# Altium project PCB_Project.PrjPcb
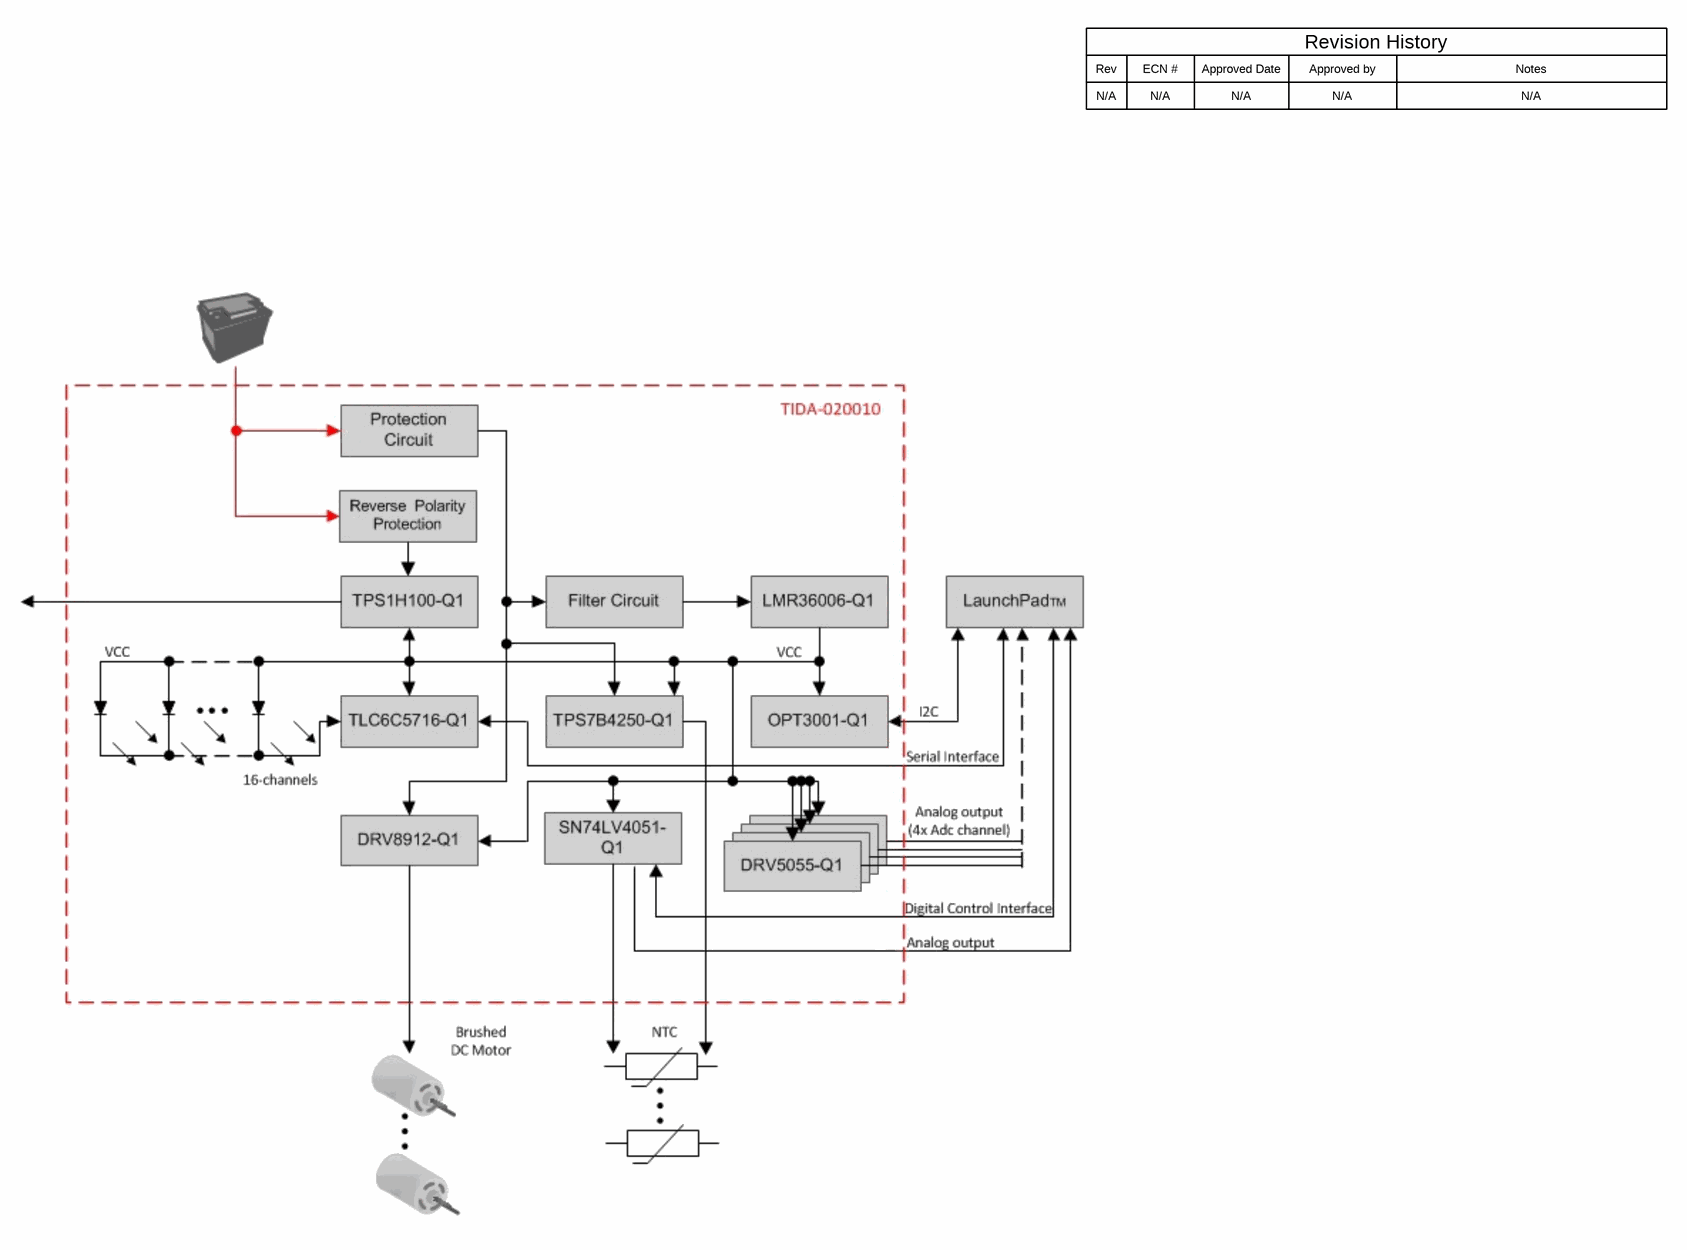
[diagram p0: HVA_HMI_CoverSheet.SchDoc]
CopyrightYear: 2018; PCB_Layout: Levan Bidzishvili; PCB_Rev: E1; PRJ_Customer: Public Release; PRJ_Engineer: Levan Bidzishvili; PRJ_Number: TIDA-020010; PRJ_Title: Automotive HVAC Control with HMI Reference Design; SCH_Rev: E1; TechSupport: http://www.ti.com/support; TID: 020010
4 sheets, 120 parts. Net scope: global (net labels, ports and power ports of the same name join across sheets).
Board file: PCB_Project_PCB.PcbDoc
Sheets:
  HVA_HMI_CoverSheet.SchDoc
  HVA_HMI_p1.SchDoc
  HVA_HMI_p2.SchDoc
  HVAC_HMI_EVM_Hardware.SchDoc

## Sheet HVA_HMI_CoverSheet.SchDoc
size 431 x 279 mm; Date: Not shown in title block; ApprovedBy: Not shown in title block; CheckedBy: Not shown in title block; Author: Not shown in title block; CompanyName: Not shown in title block; Engineer: Not shown in title block; Organization: Not shown in title block; Address1: Not shown in title block; Address2: Not shown in title block; Address3: Not shown in title block; Address4: Not shown in title block; DocumentNumber: 1; Revision: Use project parameter SCH_Rev; SheetNumber: 1; SheetTotal: 3; PageSetup: Record=PageOptions¦CenterHorizontal=True¦CenterVertical=True¦PrintScale=1.00¦XCorrection=1.00¦YCorrection=1.00¦PrintKind=0¦BorderSize=5000000¦LeftOffset=0¦BottomOffset=0¦Orientation=2¦PaperLength=1000¦PaperWidth=1000¦Scale=100¦PaperSource=15¦PrintQuality=600¦MediaType=1¦DitherType=10¦PaperKind=Letter¦PrintScaleMode=1

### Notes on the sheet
- Rev
- N/A
- ECN #
- Approved Date
- Approved by
- Revision History
- Notes

## Sheet HVA_HMI_p1.SchDoc
size 431 x 279 mm; Date: Not shown in title block; ApprovedBy: Not shown in title block; CheckedBy: Not shown in title block; Author: Not shown in title block; CompanyName: Not shown in title block; Engineer: Not shown in title block; Organization: Not shown in title block; Address1: Not shown in title block; Address2: Not shown in title block; Address3: Not shown in title block; Address4: Not shown in title block; DocumentNumber: 1; Revision: Use project parameter SCH_Rev; SheetNumber: 2; SheetTotal: 3; PageSetup: Record=PageOptions¦CenterHorizontal=True¦CenterVertical=True¦PrintScale=1.00¦XCorrection=1.00¦YCorrection=1.00¦PrintKind=0¦BorderSize=5000000¦LeftOffset=0¦BottomOffset=0¦Orientation=2¦PaperLength=1000¦PaperWidth=1000¦Scale=100¦PaperSource=15¦PrintQuality=600¦MediaType=1¦DitherType=10¦PaperKind=Letter¦PrintScaleMode=1
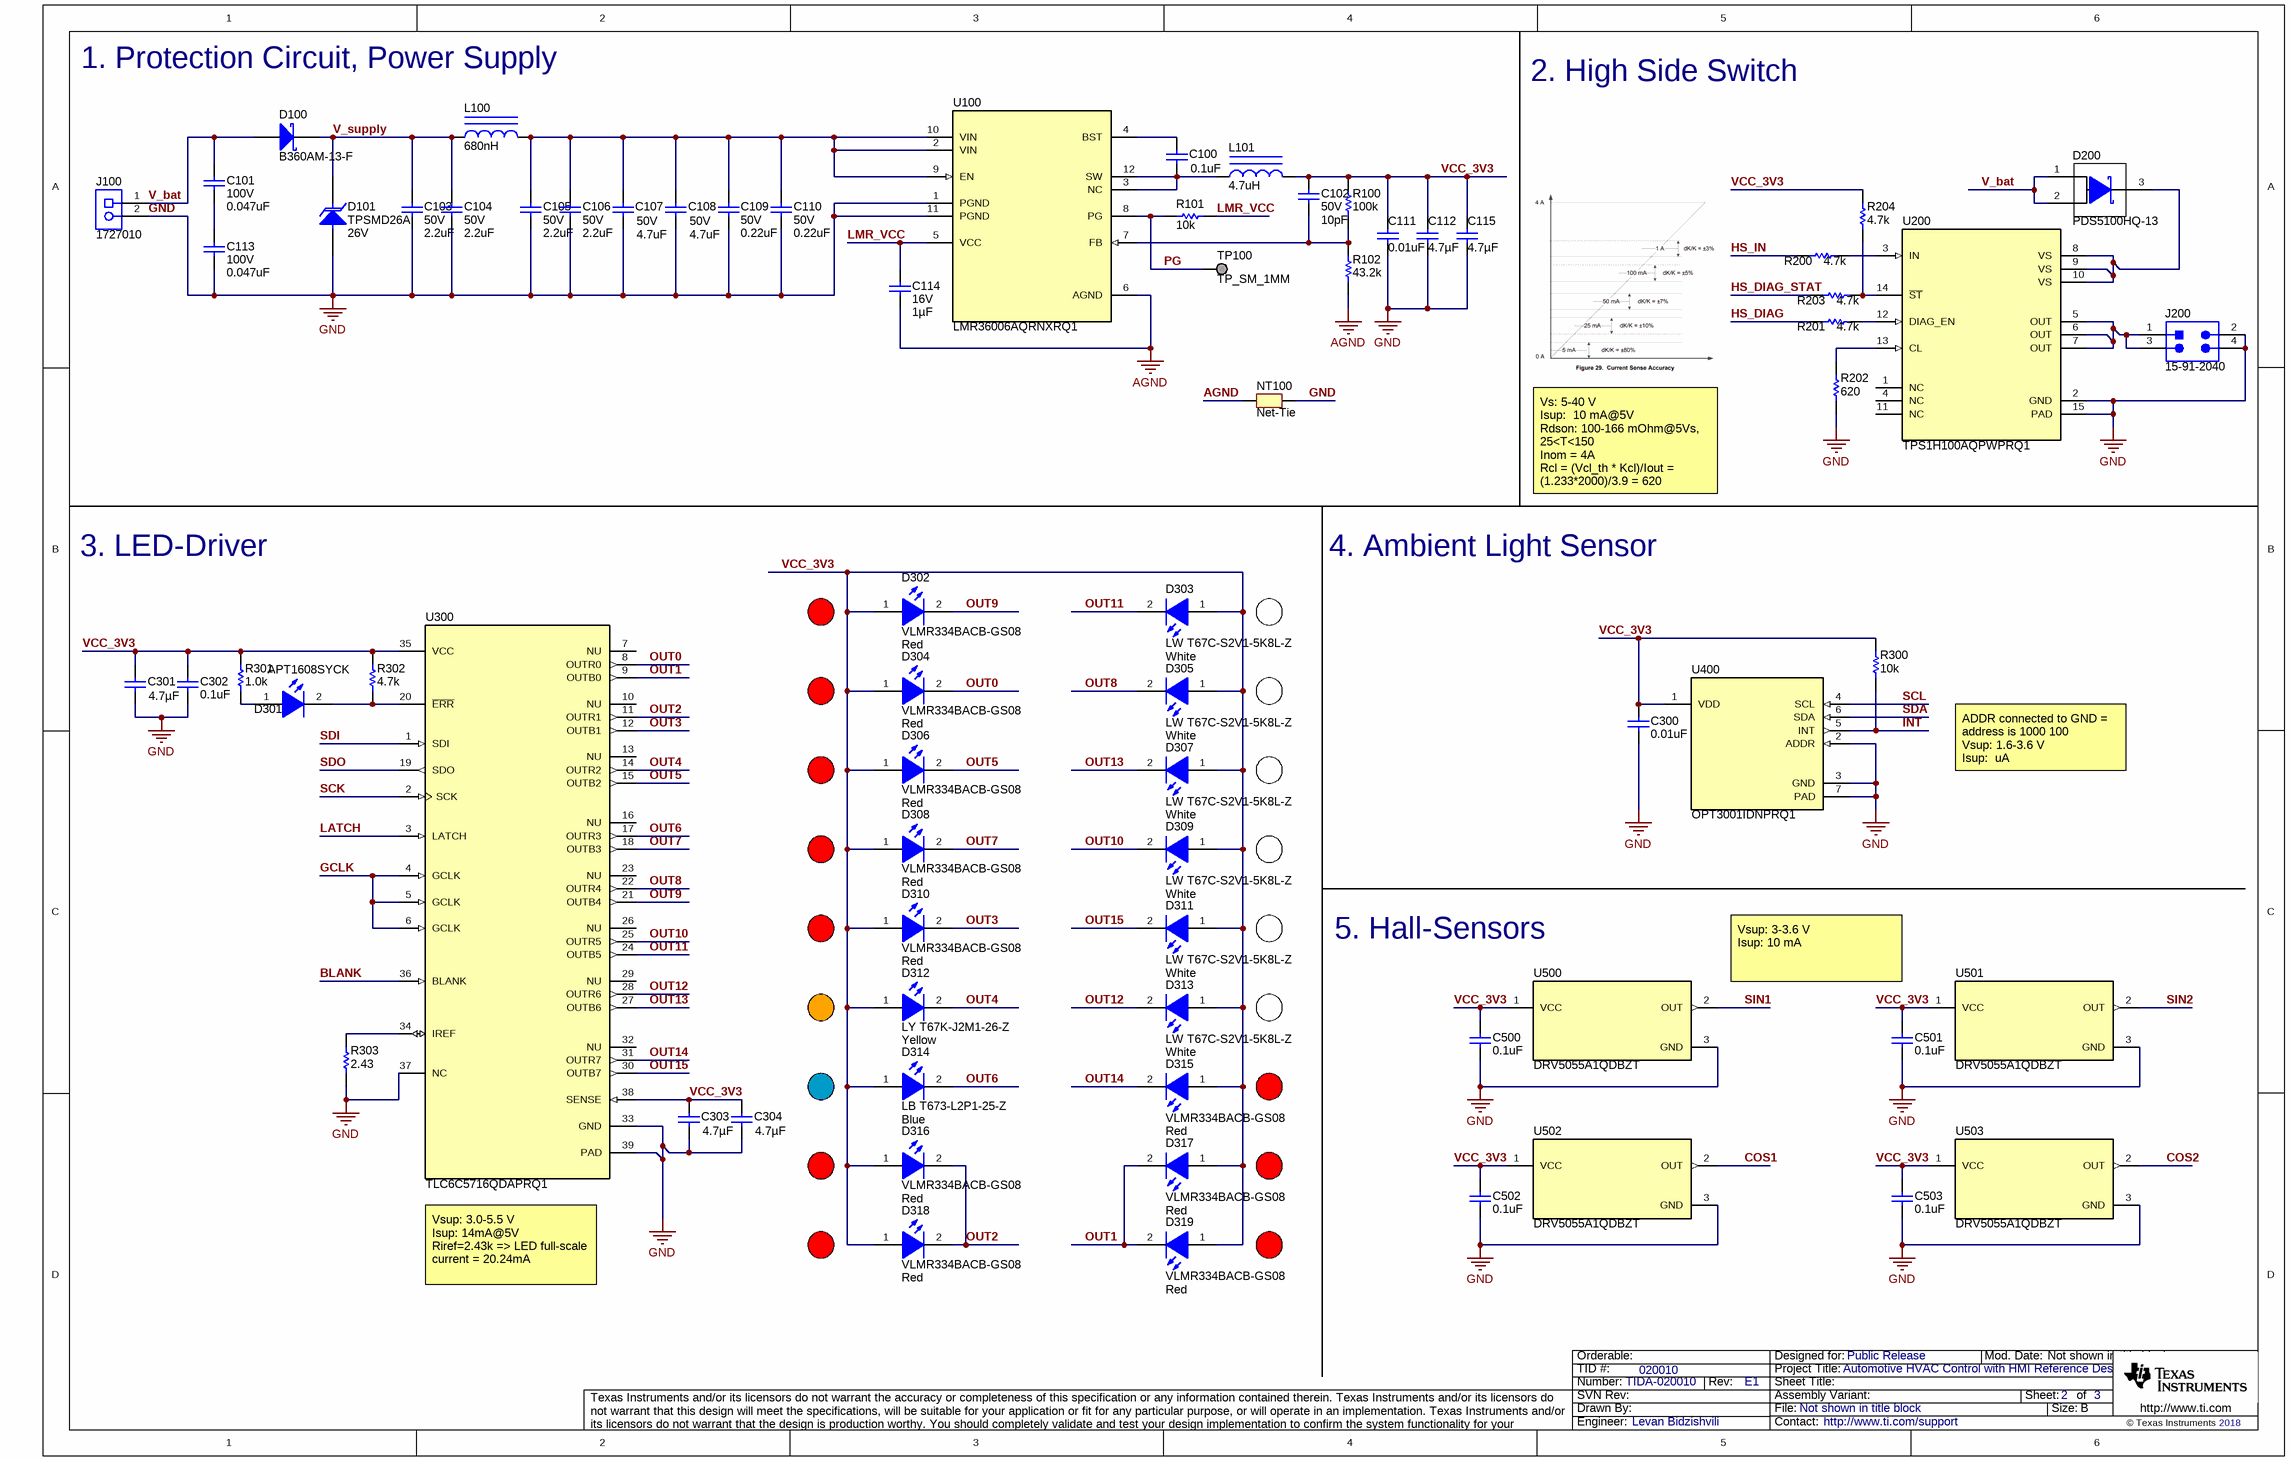
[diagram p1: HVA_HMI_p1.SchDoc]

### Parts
C100  ValueDisplayed: 0.1uF  [0603S]  (hidden comment: CGA3E2X7R1H104K080AA)
C101  VDC_V: 100V  ValueDisplayed: 0.047uF  [0805_HV]  (hidden comment: CGA4J2X7R2A473K125AA)
C102  VDC_V: 50V  ValueDisplayed: 10pF  [0603S]  (hidden comment: CGA3E2C0G1H100D080AA)
C103  VDC_V: 50V  ValueDisplayed: 2.2uF  [0805_HV]  (hidden comment: CGA4J3X7R1H225K125AB)
C104  VDC_V: 50V  ValueDisplayed: 2.2uF  [0805_HV]  (hidden comment: CGA4J3X7R1H225K125AB)
C105  VDC_V: 50V  ValueDisplayed: 2.2uF  [0805_HV]  (hidden comment: CGA4J3X7R1H225K125AB)
C106  VDC_V: 50V  ValueDisplayed: 2.2uF  [0805_HV]  (hidden comment: CGA4J3X7R1H225K125AB)
C107  VDC_V: 50V  ValueDisplayed: 4.7uF  [0805_HV]  (hidden comment: GRT21BR61H475KE13L)
C108  VDC_V: 50V  ValueDisplayed: 4.7uF  [0805_HV]  (hidden comment: GRT21BR61H475KE13L)
C109  VDC_V: 50V  ValueDisplayed: 0.22uF  [0603S]  (hidden comment: GCM188R71H224KA64D)
C110  VDC_V: 50V  ValueDisplayed: 0.22uF  [0603S]  (hidden comment: GCM188R71H224KA64D)
C111  ValueDisplayed: 0.01uF  [0603S]  (hidden comment: C0603C103J3GECAUTO)
C112  ValueDisplayed: 4.7µF  [0805_HV]  (hidden comment: CGA4J1X7R1E475K125AC)
C113  VDC_V: 100V  ValueDisplayed: 0.047uF  [0805_HV]  (hidden comment: CGA4J2X7R2A473K125AA)
C114  VDC_V: 16V  ValueDisplayed: 1µF  [0603S]  (hidden comment: CGA3E1X7R1C105K080AC)
C115  ValueDisplayed: 4.7µF  [0805_HV]  (hidden comment: CGA4J1X7R1E475K125AC)
C300  ValueDisplayed: 0.01uF  [0603]  (hidden comment: C0603C103J3GECAUTO)
C301  ValueDisplayed: 4.7µF  [0805L]  (hidden comment: CGA4J1X7R1E475K125AC)
C302  ValueDisplayed: 0.1uF  [0603]  (hidden comment: CGJ3E2X7R1C104K080AA)
C303  ValueDisplayed: 4.7µF  [0805L]  (hidden comment: CGA4J1X7R1E475K125AC)
C304  ValueDisplayed: 4.7µF  [0805L]  (hidden comment: CGA4J1X7R1E475K125AC)
C500  ValueDisplayed: 0.1uF  [0603]  (hidden comment: CGJ3E2X7R1C104K080AA)
C501  ValueDisplayed: 0.1uF  [0603]  (hidden comment: CGJ3E2X7R1C104K080AA)
C502  ValueDisplayed: 0.1uF  [0603]  (hidden comment: CGJ3E2X7R1C104K080AA)
C503  ValueDisplayed: 0.1uF  [0603]  (hidden comment: CGJ3E2X7R1C104K080AA)
D100  B360AM-13-F  [SMA]
D101  TPSMD26A  value 26V  [SMC_265]
D200  PDS5100HQ-13  [POWERDI5]
D301  APT1608SYCK  [APT1608_Yellow]
D302  VLMR334BACB-GS08  value Red  [VLMR334_Red]
D303  LW T67C-S2V1-5K8L-Z  value White  [LW_T67C_White]
D304  VLMR334BACB-GS08  value Red  [VLMR334_Red]
D305  LW T67C-S2V1-5K8L-Z  value White  [LW_T67C_White]
D306  VLMR334BACB-GS08  value Red  [VLMR334_Red]
D307  LW T67C-S2V1-5K8L-Z  value White  [LW_T67C_White]
D308  VLMR334BACB-GS08  value Red  [VLMR334_Red]
D309  LW T67C-S2V1-5K8L-Z  value White  [LW_T67C_White]
D310  VLMR334BACB-GS08  value Red  [VLMR334_Red]
D311  LW T67C-S2V1-5K8L-Z  value White  [LW_T67C_White]
D312  LY T67K-J2M1-26-Z  value Yellow  [LY_T67K_Yellow]
D313  LW T67C-S2V1-5K8L-Z  value White  [LW_T67C_White]
D314  LB T673-L2P1-25-Z  value Blue  [LB_T673_Blue]
D315  VLMR334BACB-GS08  value Red  [VLMR334_Red]
D316  VLMR334BACB-GS08  value Red  [VLMR334_Red]
D317  VLMR334BACB-GS08  value Red  [VLMR334_Red]
D318  VLMR334BACB-GS08  value Red  [VLMR334_Red]
D319  VLMR334BACB-GS08  value Red  [VLMR334_Red]
J100  1727010  [PhoenixConact_1727010]
J200  15-91-2040  [Molex_15-91-2040]
L100  ValueDisplayed: 680nH  [DFE252012P]  (hidden comment: DFE252012PD-R68M)
L101  ValueDisplayed: 4.7uH  [DFE252012P]  (hidden comment: DFE252012PD-4R7M)
NT100  Net-Tie  [Net-Tie_50milWide_30milLong]  (net tie, no BOM)
R100  ValueDisplayed: 100k  [0603S]  (hidden comment: ERJ-3GEYJ104V)
R101  ValueDisplayed: 10k  [0603S]  (hidden comment: CRCW060310K0JNEA)
R102  ValueDisplayed: 43.2k  [0603S]  (hidden comment: CRCW060343K2FKEA)
R200  ValueDisplayed: 4.7k  [0603]  (hidden comment: ERJ-3GEYJ472V)
R201  ValueDisplayed: 4.7k  [0603]  (hidden comment: ERJ-3GEYJ472V)
R202  ValueDisplayed: 620  [0805_HV]  (hidden comment: RR1220P-621-D)
R203  ValueDisplayed: 4.7k  [0603]  (hidden comment: ERJ-3GEYJ472V)
R204  ValueDisplayed: 4.7k  [0603S]  (hidden comment: ERJ-3GEYJ472V)
R300  ValueDisplayed: 10k  [0603]  (hidden comment: CRCW060310K0JNEA)
R301  ValueDisplayed: 1.0k  [0603]  (hidden comment: RCA06031K00JNEA)
R302  ValueDisplayed: 4.7k  [0603]  (hidden comment: ERJ-3GEYJ472V)
R303  ValueDisplayed: 2.43  [0603S]  (hidden comment: CRCW06032R43FKEA)
TP100  TP_SM_1MM  [TP_SM_1MM]  (no BOM)
U100  LMR36006AQRNXRQ1  [RNX0012B]
U200  TPS1H100AQPWPRQ1  [PWP0014C_N]
U300  TLC6C5716QDAPRQ1  [DAP0038E]
U400  OPT3001IDNPRQ1  [DNP0006A]
U500  DRV5055A1QDBZT  [DBZ0003A_N]
U501  DRV5055A1QDBZT  [DBZ0003A_N]
U502  DRV5055A1QDBZT  [DBZ0003A_N]
U503  DRV5055A1QDBZT  [DBZ0003A_N]

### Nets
AGND: C114.1 NT100.1 R102.1 U100.6(AGND)
GND: C103.2 C104.2 C105.2 C106.2 C107.2 C108.2 C109.2 C110.2 C111.2 C112.2 C113.2 C115.2 C300.2 C301.2 C302.2 C303.2 C304.2 C500.2 C501.2 C502.2 C503.2 D101.2(A) J100.2 J200.2 J200.4 NT100.2 R202.1 R303.1 U100.1(PGND) U100.11(PGND) U200.2(GND) U200.15(PAD) U300.33(GND) U300.37(NC) U300.39(PAD) U400.2(ADDR) U400.3(GND) U400.7(PAD) U500.3(GND) U501.3(GND) U502.3(GND) U503.3(GND)
BLANK: U300.36(BLANK)
COS1: U502.2(OUT)
COS2: U503.2(OUT)
GCLK: U300.4(GCLK) U300.5(GCLK) U300.6(GCLK)
HS_DIAG: R201.2
HS_DIAG_STAT: R203.2
HS_IN: R200.2
INT: R300.1 U400.5(INT)
LATCH: U300.3(LATCH)
LMR_VCC: C114.2 R101.2 U100.5(VCC)
OUT0: D304.2(K) U300.8(OUTR0)
OUT1: D317.2(K) D319.2(K) U300.9(OUTB0)
OUT2: D316.2(K) D318.2(K) U300.11(OUTR1)
OUT3: D310.2(K) U300.12(OUTB1)
OUT4: D312.2(K) U300.14(OUTR2)
OUT5: D306.2(K) U300.15(OUTB2)
OUT6: D314.2(K) U300.17(OUTR3)
OUT7: D308.2(K) U300.18(OUTB3)
OUT8: D305.2(K) U300.22(OUTR4)
OUT9: D302.2(K) U300.21(OUTB4)
OUT10: D309.2(K) U300.25(OUTR5)
OUT11: D303.2(K) U300.24(OUTB5)
OUT12: D313.2(K) U300.28(OUTR6)
OUT13: D307.2(K) U300.27(OUTB6)
OUT14: D315.2(K) U300.31(OUTR7)
OUT15: D311.2(K) U300.30(OUTB7)
PG: R101.1 TP100.1 U100.8(PG)
SCK: U300.2(SCK)
SCL: U400.4(SCL)
SDA: U400.6(SDA)
SDI: U300.1(SDI)
SDO: U300.19(SDO)
SIN1: U500.2(OUT)
SIN2: U501.2(OUT)
V_bat: C101.1 D100.2(A) D200.1(A) D200.2(A) J100.1
V_supply: C103.1 C104.1 D100.1(K) D101.1(K) L100.1
VCC_3V3: C102.1 C111.1 C112.1 C115.1 C300.1 C301.1 C302.1 C303.1 C304.1 C500.1 C501.1 C502.1 C503.1 D302.1(A) D303.1(A) D304.1(A) D305.1(A) D306.1(A) D307.1(A) D308.1(A) D309.1(A) D310.1(A) D311.1(A) D312.1(A) D313.1(A) D314.1(A) D315.1(A) D316.1(A) D317.1(A) D318.1(A) D319.1(A) L101.2 R100.2 R204.2 R300.2 R301.2 R302.1 U300.35(VCC) U300.38(SENSE) U400.1(VDD) U500.1(VCC) U501.1(VCC) U502.1(VCC) U503.1(VCC)
NetC100_1: C100.1 L101.1 U100.3(NC) U100.12(SW)
NetC100_2: C100.2 U100.4(BST)
NetC101_2: C101.2 C113.1
NetC102_2: C102.2 R100.1 R102.2 U100.7(FB)
NetC105_1: C105.1 C106.1 C107.1 C108.1 C109.1 C110.1 L100.2 U100.2(VIN) U100.9(EN) U100.10(VIN)
NetD200_3: D200.3(K) U200.8(VS) U200.9(VS) U200.10(VS)
NetD301_1: D301.1(A) R301.1
NetD301_2: D301.2(K) R302.2 U300.20(~{ERR})
NetJ200_1: J200.1 J200.3 U200.5(OUT) U200.6(OUT) U200.7(OUT)
NetR200_1: R200.1 U200.3(IN)
NetR201_1: R201.1 U200.12(DIAG_EN)
NetR202_2: R202.2 U200.13(CL)
NetR203_1: R203.1 R204.1 U200.14(~{ST})
NetR303_2: R303.2 U300.34(IREF)

Not connected (* = marked no-connect by the designer): U200 1(NC) 4(NC) 11(NC); U300 7(NU) 10(NU) 13(NU) 16(NU) 23(NU) 26(NU) 29(NU) 32(NU)

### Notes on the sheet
- 1. Protection Circuit, Power Supply
- 2. High Side Switch
- standoff voltage should be above 24V because of jump-start condition. better would be 26V
  SMAJ26CAHE3/61 VISHAY
  TPS... littlefuse
- (near R102) voltage devider is a place holder
- 06A: 600mA, 400kHz
  06C: 600ma, 2.1Mhz
  FSC3: my choice
- Vs: 5-40 V
  Isup:  10 mA@5V
  Rdson: 100-166 mOhm@5Vs, 25<T<150
  Inom = 4A
  Rcl = (Vcl_th * Kcl)/Iout = (1.233*2000)/3.9 = 620
- 3. LED-Driver
- 4. Ambient Light Sensor
- (near D302) LED's are place holders here.
  they should choosen properly
- ADDR connected to GND = address is 1000 100
  Vsup: 1.6-3.6 V
  Isup:  uA
- 5. Hall-Sensors
- Vsup: 3-3.6 V
  Isup: 10 mA
- (near C304) Sense wire is connected to source rail (V_3V3) in this case.
- Vsup: 3.0-5.5 V
  Isup: 14mA@5V
  Riref=2.43k => LED full-scale current = 20.24mA

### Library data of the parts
C100 = CMP-0007078-4: CAP, CERM, 0.1 uF, 50 V, +/- 10%, X7R, AEC-Q200 Grade 1, 0603; Manufacturer: TDK; TaMin_C: -55°C; Polarized: N; SizeAreaWB_mm2: 4.68; Value1: 0.0296 ohm; U/M: EA; Value: 0.1uF; TaMax_C: 125°C; SizeZ_mm: 1; SizeX_mm: 1.6; SizeY_mm: 0.8; Cap_Case: 0603; Value2: 50V; SizeArea_mm2: 1.28; CompType: Capacitor; AEC Qualified: Y; Cap_F: 100nF; AEC Category: Q200; ESR_ohm: 0.0296; IRMS_A: 9.7199dA
C101 C113 = CMP-0007970-2: CAP, CERM, 0.047 uF, 100 V, +/- 10%, X7R, AEC-Q200 Grade 1, 0805; Manufacturer: TDK; TaMin_C: -55°C; ESR_ohm: 0.049089; Polarized: N; SizeAreaWB_mm2: 6.75; Value1: 0.049089 ohm; U/M: EA; TaMax_C: 125°C; SizeZ_mm: 1.45; SizeX_mm: 2; SizeY_mm: 1.25; Cap_Case: 0805; SizeArea_mm2: 2.5; CompType: Capacitor; AEC Qualified: Y; Cap_F: 47nF; IRMS_A: 9.63171dA; AEC Grade: 1; AEC Category: Q200
C102 = CMP-0007069-4: CAP, CERM, 10 pF, 50 V, +/- 5%, C0G/NP0, AEC-Q200 Grade 1, 0603; Manufacturer: TDK; TaMin_C: -55°C; Polarized: N; SizeAreaWB_mm2: 4.68; Value1: Unknown; U/M: EA; Value: 10pF; TaMax_C: 125°C; SizeZ_mm: 1; SizeX_mm: 1.6; SizeY_mm: 0.8; Cap_Case: 0603; SizeArea_mm2: 1.28; CompType: Capacitor; AEC Qualified: Y; AEC Category: Q200
C103-C106 = CMP-0007977-2: CAP, CERM, 2.2 uF, 50 V, +/- 10%, X7R, AEC-Q200 Grade 1, 0805; Manufacturer: TDK; TaMin_C: -55°C; ESR_ohm: 3.288m; Polarized: N; SizeAreaWB_mm2: 6.75; Value1: 0.003288 ohm; U/M: EA; Value: 2.2uF; TaMax_C: 125°C; SizeZ_mm: 1.45; SizeX_mm: 2; SizeY_mm: 1.25; Cap_Case: 0805; SizeArea_mm2: 2.5; AEC Qualified: Y; Cap_F: 2.2µF; IRMS_A: 3.60029A; AEC Grade: 1; AEC Category: Q200
C107 C108 = CMP-0008380-2: CAP, CERM, 4.7 uF, 50 V, +/- 10%, X5R, AEC-Q200 Grade 3, 0805; Manufacturer: MuRata; TaMin_C: -55°C; Polarized: N; SizeAreaWB_mm2: 6.75; Value1: Unknown; U/M: EA; Value: 4.7uF; TaMax_C: 85°C; SizeZ_mm: 1.45; SizeX_mm: 2; SizeY_mm: 1.25; Cap_Case: 0805; SizeArea_mm2: 2.5; CompType: Capacitor; AEC Qualified: Y; Cap_F: 4.7µF; AEC Grade: 3; AEC Category: Q200
C109 C110 = CMP-0007145-4: CAP, CERM, 0.22 uF, 50 V, +/- 10%, X7R, AEC-Q200 Grade 1, 0603; Manufacturer: MuRata; TaMin_C: -55°C; Polarized: N; SizeAreaWB_mm2: 4.68; Value1: Unknown; U/M: EA; Value: 0.22uF; TaMax_C: 125°C; SizeZ_mm: 1; SizeX_mm: 1.6; SizeY_mm: 0.8; Cap_Case: 0603; SizeArea_mm2: 1.28; CompType: Capacitor; AEC Qualified: Y; Cap_F: 220nF; AEC Category: Q200
C111 = CMP-0006849-4: CAP, CERM, 0.01 uF, 25 V, +/- 5%, C0G/NP0, AEC-Q200 Grade 1, 0603; Manufacturer: Kemet; TaMin_C: -55°C; Polarized: N; SizeAreaWB_mm2: 4.68; Value1: Unknown; U/M: EA; Value: 0.01uF; TaMax_C: 125°C; SizeZ_mm: 1; SizeX_mm: 1.6; SizeY_mm: 0.8; Cap_Case: 0603; Value2: 25V; SizeArea_mm2: 1.28; CompType: Capacitor; AEC Qualified: Y; Cap_F: 10nF; AEC Category: Q200
C112 C115 C301 C303 C304 = CMP-0076706-1: CAP, CERM, 4.7 µF, 25 V,+/- 10%, X7R, AEC-Q200 Grade 1, 0805; Manufacturer: TDK; SizeAreaWB_mm2: 6.75; SizeArea_mm2: 2.5; AEC Qualified: Y; AEC Category: Q200; Value: 4.7uF; TaMax_C: 125°C; SizeZ_mm: 1.45; AEC Grade: 1; Polarized: N; TaMin_C: -55°C; VDC_V: 25V; SizeY_mm: 1.25; U/M: EA; CompType: Capacitor; SizeX_mm: 2.0; Cap_Case: 2x1.25x1.25mm
C114 = CMP-0079607-1: CAP, CERM, 1 µF, 16 V,+/- 10%, X7R, AEC-Q200 Grade 1, 0603; Manufacturer: TDK; TaMin_C: -55°C; Polarized: N; SizeAreaWB_mm2: 4.68; U/M: EA; Value: 1uF; TaMax_C: 125°C; SizeZ_mm: 1; SizeX_mm: 1.6; SizeY_mm: 0.8; Cap_Case: 0603; SizeArea_mm2: 1.28; CompType: Capacitor; AEC Qualified: Y; AEC Category: Q200
C300 = CMP-0006849-4: CAP, CERM, 0.01 uF, 25 V, +/- 5%, C0G/NP0, AEC-Q200 Grade 1, 0603; Manufacturer: Kemet; TaMin_C: -55°C; Polarized: N; SizeAreaWB_mm2: 4.68; Value1: Unknown; U/M: EA; Value: 0.01uF; TaMax_C: 125°C; SizeZ_mm: 1; SizeX_mm: 1.6; SizeY_mm: 0.8; Value2: 25V; SizeArea_mm2: 1.28; CompType: Capacitor; AEC Qualified: Y; Cap_F: 10nF; AEC Category: Q200
C302 C500-C503 = CMP-0007106-4: CAP, CERM, 0.1 uF, 16 V, +/- 10%, X7R, AEC-Q200 Grade 1, 0603; Manufacturer: TDK; TaMin_C: -55°C; Polarized: N; SizeAreaWB_mm2: 4.68; Value1: Unknown; U/M: EA; Value: 0.1uF; TaMax_C: 125°C; SizeZ_mm: 1; SizeX_mm: 1.6; SizeY_mm: 0.8; Value2: 16V; SizeArea_mm2: 1.28; CompType: Capacitor; AEC Qualified: Y; Cap_F: 100nF; AEC Category: Q200
D100 = CMP-0028785-1: Diode, Schottky, 60 V, 3 A, AEC-Q101, SMA; Manufacturer: Diodes Inc.; Io_A: 3A; Green_Lifecycle: Not Set; SizeAreaWB_mm2: 37.3428; Vr_V: 60V; Green_REACh: Incomplete; TJmax_C: 150°C; U/M: EA; Value: 60V; SizeZ_mm: 2.87; SizeX_mm: 5.59; SizeY_mm: 2.92; Vf_V: 7dV; Value2: 0.7V; SizeArea_mm2: 16.3228; AEC Qualified: Y; AEC Category: Q101
D101 = CMP-0005729-2: Diode, TVS, Uni, 26 V, 42.1 Vc, AEC-Q101, SMC; Manufacturer: Littelfuse; Power_W: 6.5W; SizeAreaWB_mm2: 78.5757; RJA_CperW: 75; U/M: EA; SizeZ_mm: 2.62; SizeX_mm: 7.94; SizeY_mm: 5.905; SizeArea_mm2: 46.8857; AEC Qualified: Y; AEC Category: Q101
D200 = CMP-0080010-1: Diode, Schottky, 100 V, 5 A, AEC-Q101, PowerDI5; Manufacturer: Diodes Inc.; SizeAreaWB_mm2: 49.56; Vr_V: 100V; SizeArea_mm2: 24.96; AEC Qualified: Y; TJmax_C: 175°C; AEC Category: Q101; Value: 100V; SizeZ_mm: 1.05; Io_A: 5A; Vf_V: 7.1dV; SizeY_mm: 3.9; Value2: 0.71V; SizeX_mm: 6.4; RJC_CperW: 5
D301 = CMP-0002944-2: LED, Yellow, SMD; Manufacturer: Kingbright; Io_A: 20mA; Vr_V: 5V; Tjmax_C: 85°C; Value1: W; U/M: EA; Angle: 120; Ir_A: 10µA; Vf_V: 2.5V
D302 D304 D306 D308 D310 D315-D319 = CMP-0067668-1: LED, Red, SMD; Manufacturer: Vishay-Semiconductor; Io_A: 50mA; Power_TotalModule: 200mW; SizeAreaWB_mm2: 17.1; Vr_V: 5V; Tjmax_C: 125°C; Value1: 0.2W; U/M: EA; Angle: 120.0; SizeZ_mm: 1.85; SizeX_mm: 3.5; SizeY_mm: 2.8; Ir_A: 10µA; Vf_V: 2.2V; SizeArea_mm2: 9.8; Type: AlInGaP
D303 D305 D307 D309 D311 D313 = CMP-0003011-2: LED, White, SMD; Manufacturer: OSRAM; Io_A: 20mA; SizeAreaWB_mm2: 17.1; Vr_V: 5V; Tjmax_C: 110°C; Value1: W; U/M: EA; Angle: 120; SizeZ_mm: 2.1; SizeX_mm: 2.8; SizeY_mm: 3.5; Ir_A: 10µA; Vf_V: 3.2V; SizeArea_mm2: 9.8; Type: InGaN
D312 = CMP-0003012-2: LED, Yellow, SMD; Manufacturer: OSRAM; Io_A: 20mA; SizeAreaWB_mm2: 17.1; Vr_V: 12V; Tjmax_C: 125°C; Value1: W; U/M: EA; Angle: 120; SizeZ_mm: 2.1; SizeX_mm: 2.8; SizeY_mm: 3.5; Ir_A: 10µA; Vf_V: 1.8V; SizeArea_mm2: 9.8; Type: AlInGaP
D314 = CMP-0003013-2: LED, Blue, SMD; Manufacturer: OSRAM; Io_A: 20mA; SizeAreaWB_mm2: 17.1; Vr_V: 5V; Tjmax_C: 110°C; Value1: W; U/M: EA; Angle: 120; SizeZ_mm: 2.1; SizeX_mm: 2.8; SizeY_mm: 3.5; Ir_A: 10µA; Vf_V: 3.1V; SizeArea_mm2: 9.8; Type: InGaN
J100 = CMP-0055472-1: Conn Term Block, 2POS, 3.81mm, TH; Manufacturer: Phoenix Contact; CT: TRUE; Green_REACh: Incomplete; CompType: Terminal Block; CNHeader: FALSE; Green_Lifecycle: Not Set
J200 = CMP-0055317-1: Header, 100mil, 2x2, Tin, SMT; Manufacturer: Molex; CNHeader: TRUE; Green_Lifecycle: Active; Green_REACh: Passed; CT: FALSE
L100 = CMP-0058945-1: Inductor, Shielded, Metal Composite, 680 nH, 3.5 A, 0.03 ohm, AEC-Q200 Grade 1, SMD; Manufacturer: MuRata Toko; Isat: 4.3A @ 30% inductance drop; Irms: 3.5A @ 40C rise; SizeAreaWB_mm2: 10.5; DCR_ohm: 0.03; Value: 680nH; Imax_A: 3.5A; SizeZ_mm: 1.2; SizeX_mm: 2.5; SizeY_mm: 2; SizeArea_mm2: 5; AEC Qualified: Y; AEC Grade: 1; AEC Category: Q200
L101 = CMP-0058942-1: Inductor, Shielded, Metal Composite, 4.7 uH, 1.4 A, 0.165 ohm, AEC-Q200 Grade 1, SMD; Manufacturer: MuRata Toko; Isat: 1.9A @ 30% inductance drop; Irms: 1.4A @ 40C rise; SizeAreaWB_mm2: 10.5; DCR_ohm: 1.65d; Value: 4.7uH; Imax_A: 1.4A; SizeZ_mm: 1.2; SizeX_mm: 2.5; SizeY_mm: 2; SizeArea_mm2: 5; Ind_H: 4.7µH; AEC Qualified: Y; AEC Grade: 1; AEC Category: Q200
NT100 = CMP-0078142-2: Single point connection between nets.
R100 = CMP-0025875-3: RES, 100 k, 5%, 0.1 W, AEC-Q200 Grade 0, 0603; Manufacturer: Panasonic; Power_W: 100mW; TempCo: 200 ppm/C; U/M: EA; Value: 100k; EIA_Code: E24; SizeX_mm: 1.6; SizeY_mm: 0.8; SizeZ_mm: 1; Value2: 0.1W; SizeArea_mm2: 1.28; CompType: Resistor; AEC Qualified: Y; VDC_V: 50V; AEC Grade: 0; AEC Category: Q200
R101 = CMP-0025701-4: RES, 10 k, 5%, 0.1 W, AEC-Q200 Grade 0, 0603; Manufacturer: Vishay-Dale; Power_W: 100mW; TempCo: 200 ppm/C; Value_Code: 10k0; Value: 10k; EIA_Code: E24; SizeX_mm: 1.6; SizeY_mm: 0.8; SizeZ_mm: 1; Value2: 0.1W; SizeArea_mm2: 1.28; CompType: Resistor; AEC Qualified: Y; VDC_V: 75V; AEC Category: Q200; AEC Grade: 0
R102 = CMP-0022422-4: RES, 43.2 k, 1%, 0.1 W, AEC-Q200 Grade 0, 0603; Manufacturer: Vishay-Dale; Power_W: 100mW; TempCo: 100 ppm/C; Value_Code: 43k2; Value: 43.2k; EIA_Code: E96; SizeX_mm: 1.6; SizeY_mm: 0.8; SizeZ_mm: 1; Value2: 0.1W; SizeArea_mm2: 1.28; CompType: Resistor; AEC Qualified: Y; VDC_V: 75V; AEC Category: Q200; AEC Grade: 0
R200 R201 R203 R302 = CMP-0025881-3: RES, 4.7 k, 5%, 0.1 W, AEC-Q200 Grade 0, 0603; Manufacturer: Panasonic; Power_W: 100mW; TempCo: 200 ppm/C; Value_Code: 4k70; U/M: EA; Value: 4.7k; EIA_Code: E24; SizeX_mm: 1.6; SizeY_mm: 0.8; SizeZ_mm: 1; Value2: 0.1W; SizeArea_mm2: 1.28; AEC Qualified: Y; VDC_V: 75V; AEC Grade: 0; AEC Category: Q200
R202 = CMP-0019338-2: RES, 620, 0.5%, 0.1 W, 0805; Manufacturer: Susumu Co Ltd; Power_W: 100mW; TempCo: 25 ppm/C; Value_Code: 620R; U/M: EA; Value: 620; SizeX_mm: 2; SizeY_mm: 1.25; SizeZ_mm: 1.45; Value2: 0.1W; SizeArea_mm2: 2.5; VDC_V: 100V; AEC Category: Q200
R204 = CMP-0025881-3: RES, 4.7 k, 5%, 0.1 W, AEC-Q200 Grade 0, 0603; Manufacturer: Panasonic; Power_W: 100mW; TempCo: 200 ppm/C; Value_Code: 4k70; U/M: EA; Value: 4.7k; EIA_Code: E24; SizeX_mm: 1.6; SizeY_mm: 0.8; SizeZ_mm: 1; Value2: 0.1W; SizeArea_mm2: 1.28; CompType: Resistor; AEC Qualified: Y; VDC_V: 75V; AEC Grade: 0; AEC Category: Q200
R300 = CMP-0025701-4: RES, 10 k, 5%, 0.1 W, AEC-Q200 Grade 0, 0603; Manufacturer: Vishay-Dale; Power_W: 100mW; TempCo: 200 ppm/C; Value_Code: 10k0; Value: 10k; EIA_Code: E24; SizeX_mm: 1.6; SizeY_mm: 0.8; SizeZ_mm: 1; Value2: 0.1W; SizeArea_mm2: 1.28; AEC Qualified: Y; VDC_V: 75V; AEC Category: Q200; AEC Grade: 0
R301 = CMP-0025946-3: RES, 1.0 k, 5%, 0.1 W, AEC-Q200 Grade 0, 0603; Manufacturer: Vishay-Dale; Power_W: 100mW; TempCo: 200 ppm/C; Value_Code: 1k00; U/M: EA; Value: 1.0k; EIA_Code: E24; Res_ohm: 1k; SizeX_mm: 1.6; SizeY_mm: 0.8; SizeZ_mm: 1; Value2: 0.1W; SizeArea_mm2: 1.28; AEC Qualified: Y; VDC_V: 75V; AEC Grade: 0; AEC Category: Q200
R303 = CMP-0022310-4: RES, 2.43, 1%, 0.1 W, AEC-Q200 Grade 0, 0603; Manufacturer: Vishay-Dale; Power_W: 100mW; TempCo: 100 ppm/C; Value_Code: 2R43; Value: 2.43; EIA_Code: E96; SizeX_mm: 1.6; SizeY_mm: 0.8; SizeZ_mm: 1; Value2: 0.1W; SizeArea_mm2: 1.28; CompType: Resistor; AEC Qualified: Y; VDC_V: 75V; AEC Category: Q200; AEC Grade: 0
TP100 = CMP-0003825-1: 1mm Test Point, SMT; Manufacturer: Any
U100 = CMP-0077180-4: Automotive 65-V 0.6-A Synchronous Step-Down Converter, RNX0012B (VQFN-HR-12); Manufacturer: Texas Instruments; Alternate PartNumber: LMR36006AQRNXTQ1; SizeX_mm: 2.0; SizeY_mm: 3.0; CompType: IC; SizeZ_mm: 1.0; AEC Qualified: Y; SizeArea_mm2: 6.0; AEC Category: Q200; SizeAreaWB_mm2: 12.0
U200 = CMP-0073689-2: 40V/100mOhm Single Channel Smart High Side Switch, PWP0014C (TSSOP-14); Manufacturer: Texas Instruments; SizeX_mm: 6.4; SizeY_mm: 5.0; CompType: IC; SizeZ_mm: 1.2; SizeArea_mm2: 32.0; SizeAreaWB_mm2: 58.8; U/M: EA
U300 = CMP-0078396-2: Automotive Grade 16-Channel, Full Diagnostics, Constant-Current LED Driver with 7-Bit Dot Correction and 12-Bit PWM Dimming, DAP0038E (TSSOP-38); Manufacturer: Texas Instruments; SizeZ_mm: 1.2; SizeX_mm: 8.1; SizeY_mm: 12.5; AEC Category: Q200; AEC Qualified: Y; SizeArea_mm2: 101.25; CompType: IC; SizeAreaWB_mm2: 146.45
U400 = CMP-0074867-2: Ambient Light Sensor (ALS), DNP0006A (USON-6); Alternate PartNumber: OPT3001IDNPTQ1; Alternate Manufacturer: Texas Instruments; SizeAreaWB_mm2: 9.0; U/M: EA; SizeZ_mm: 0.65; SizeX_mm: 2.0; SizeArea_mm2: 4.0; CompType: IC
U500-U503 = CMP-0081694-1: High Accuracy 3.3 V or 5 V Ratiometric Bipolar Hall Effect Sensor Family, DBZ0003A (SOT-23-3); Alternate PartNumber: DRV5055A1QDBZR; Alternate Manufacturer: Texas Instruments; SizeAreaWB_mm2: 14; Rating: Catalog; SizeZ_mm: 1.12; SizeX_mm: 2.5; SizeY_mm: 3; SizeArea_mm2: 7.5; CompType: IC; AEC Qualified: N; AEC Category: Q200

## Sheet HVA_HMI_p2.SchDoc
size 431 x 279 mm; Date: Not shown in title block; ApprovedBy: Not shown in title block; CheckedBy: Not shown in title block; Author: Not shown in title block; CompanyName: Not shown in title block; Engineer: Not shown in title block; Organization: Not shown in title block; Address1: Not shown in title block; Address2: Not shown in title block; Address3: Not shown in title block; Address4: Not shown in title block; DocumentNumber: 1; Revision: Use project parameter SCH_Rev; SheetNumber: 2; SheetTotal: 3; PageSetup: Record=PageOptions¦CenterHorizontal=True¦CenterVertical=True¦PrintScale=1.00¦XCorrection=1.00¦YCorrection=1.00¦PrintKind=0¦BorderSize=5000000¦LeftOffset=0¦BottomOffset=0¦Orientation=2¦PaperLength=1000¦PaperWidth=1000¦Scale=100¦PaperSource=15¦PrintQuality=600¦MediaType=1¦DitherType=10¦PaperKind=Letter¦PrintScaleMode=1
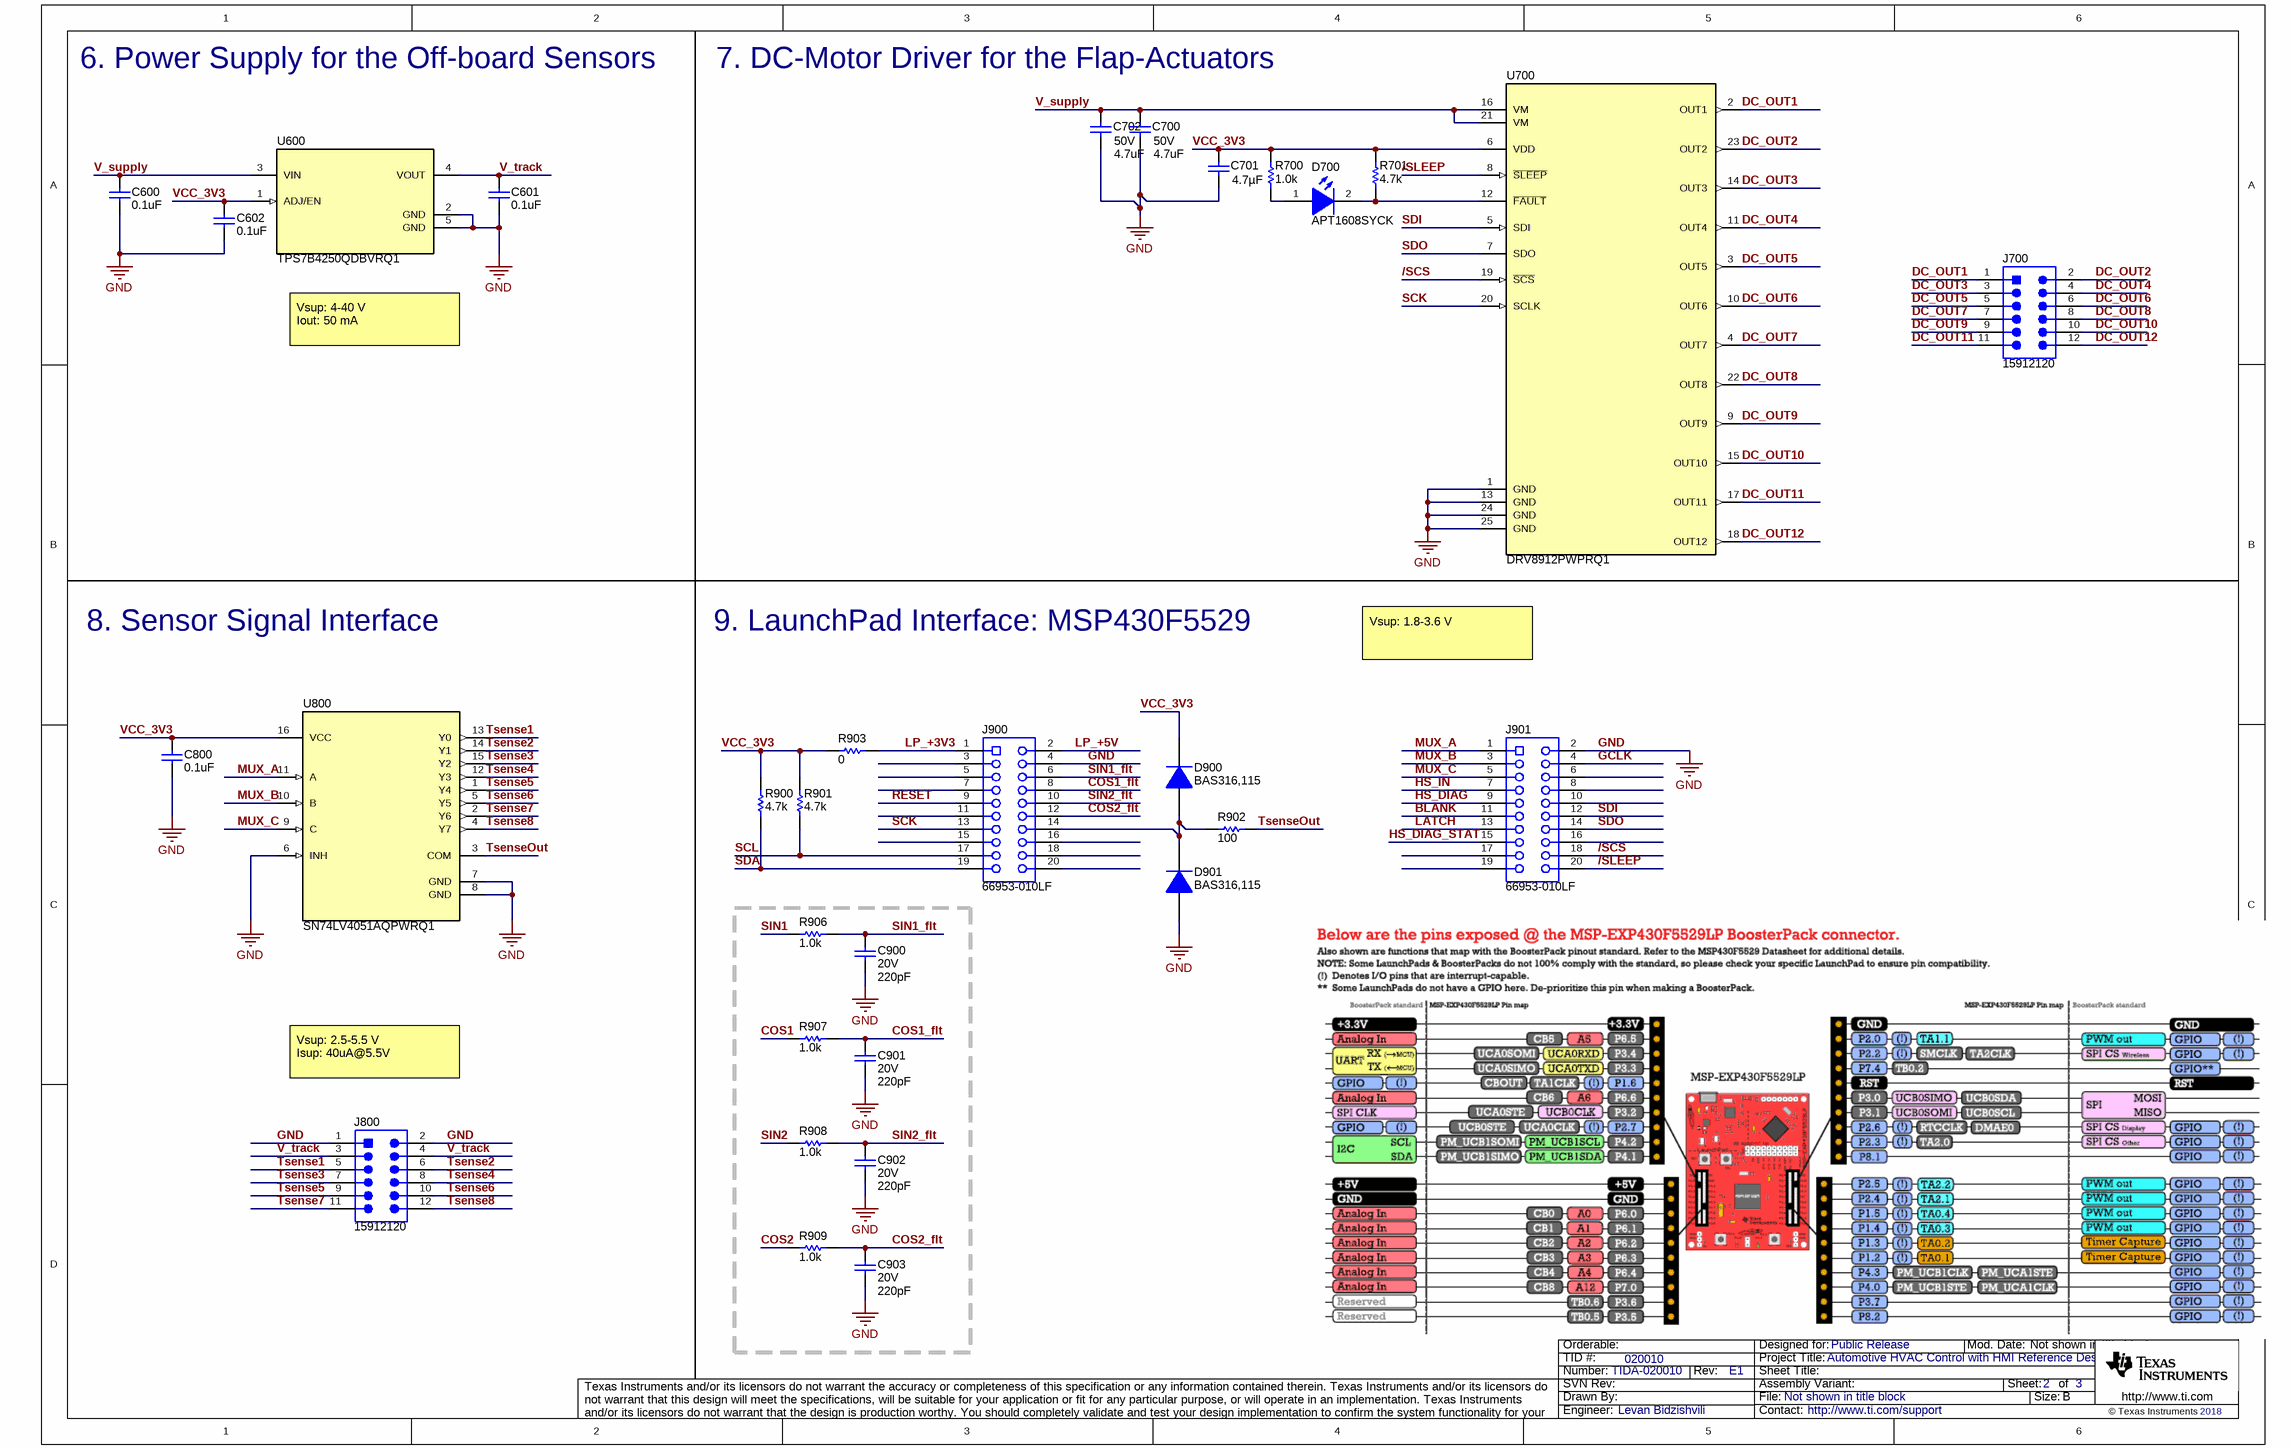
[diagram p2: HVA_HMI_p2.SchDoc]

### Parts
C600  ValueDisplayed: 0.1uF  [0805_HV]  (hidden comment: GCM21BR71H104KA37K)
C601  ValueDisplayed: 0.1uF  [0805_HV]  (hidden comment: GCM21BR71H104KA37K)
C602  ValueDisplayed: 0.1uF  [0603]  (hidden comment: CGJ3E2X7R1C104K080AA)
C700  VDC_V: 50V  ValueDisplayed: 4.7uF  [0805_HV]  (hidden comment: GRT21BR61H475KE13L)
C701  ValueDisplayed: 4.7µF  [0805L]  (hidden comment: CGA4J1X7R1E475K125AC)
C702  VDC_V: 50V  ValueDisplayed: 4.7uF  [0805_HV]  (hidden comment: GRT21BR61H475KE13L)
C800  ValueDisplayed: 0.1uF  [0603]  (hidden comment: CGJ3E2X7R1C104K080AA)
C900  VDC_V: 20V  ValueDisplayed: 220pF  [0603]  (hidden comment: CGA3E2C0G1H221J080AA)
C901  VDC_V: 20V  ValueDisplayed: 220pF  [0603]  (hidden comment: CGA3E2C0G1H221J080AA)
C902  VDC_V: 20V  ValueDisplayed: 220pF  [0603]  (hidden comment: CGA3E2C0G1H221J080AA)
C903  VDC_V: 20V  ValueDisplayed: 220pF  [0603]  (hidden comment: CGA3E2C0G1H221J080AA)
D700  APT1608SYCK  [APT1608_Yellow]
D900  BAS316,115  [SOD-323]
D901  BAS316,115  [SOD-323]
J700  15912120  [MOLEX_0015912120]
J800  15912120  [MOLEX_0015912120]
J900  66953-010LF  [FCI_66953-010LF]
J901  66953-010LF  [FCI_66953-010LF]
R700  ValueDisplayed: 1.0k  [0603]  (hidden comment: RCA06031K00JNEA)
R701  ValueDisplayed: 4.7k  [0603]  (hidden comment: ERJ-3GEYJ472V)
R900  ValueDisplayed: 4.7k  [0603S]  (hidden comment: ERJ-3GEYJ472V)
R901  ValueDisplayed: 4.7k  [0603S]  (hidden comment: ERJ-3GEYJ472V)
R902  ValueDisplayed: 100  [0603]  (hidden comment: CRCW0603100RJNEA)
R903  ValueDisplayed: 0  [0805_HV]  (hidden comment: CRCW08050000Z0EA)
R906  ValueDisplayed: 1.0k  [0603]  (hidden comment: RCA06031K00JNEA)
R907  ValueDisplayed: 1.0k  [0603]  (hidden comment: RCA06031K00JNEA)
R908  ValueDisplayed: 1.0k  [0603]  (hidden comment: RCA06031K00JNEA)
R909  ValueDisplayed: 1.0k  [0603]  (hidden comment: RCA06031K00JNEA)
U600  TPS7B4250QDBVRQ1  [DBV0005A_N]
U700  DRV8912PWPRQ1  [PWP0024J_N]
U800  SN74LV4051AQPWRQ1  [PW0016A_N]

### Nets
GND: C600.2 C601.2 C602.2 C700.2 C701.2 C702.2 C800.2 C900.2 C901.2 C902.2 C903.2 D901.2(A) J800.1 J800.2 J900.4 J901.2 U600.2(GND) U600.5(GND) U700.1(GND) U700.13(GND) U700.24(GND) U700.25(GND) U800.6(INH) U800.7(GND) U800.8(GND)
/SCS: J901.18 U700.19(~{SCS})
/SLEEP: J901.20 U700.8(~{SLEEP})
BLANK: J901.11
COS1: R907.2
COS1_flt: C901.1 J900.8 R907.1
COS2: R909.2
COS2_flt: C903.1 J900.12 R909.1
DC_OUT1: J700.1 U700.2(OUT1)
DC_OUT2: J700.2 U700.23(OUT2)
DC_OUT3: J700.3 U700.14(OUT3)
DC_OUT4: J700.4 U700.11(OUT4)
DC_OUT5: J700.5 U700.3(OUT5)
DC_OUT6: J700.6 U700.10(OUT6)
DC_OUT7: J700.7 U700.4(OUT7)
DC_OUT8: J700.8 U700.22(OUT8)
DC_OUT9: J700.9 U700.9(OUT9)
DC_OUT10: J700.10 U700.15(OUT10)
DC_OUT11: J700.11 U700.17(OUT11)
DC_OUT12: J700.12 U700.18(OUT12)
GCLK: J901.4
HS_DIAG: J901.9
HS_DIAG_STAT: J901.15
HS_IN: J901.7
LATCH: J901.13
LP_+3V3: J900.1 R903.2
LP_+5V: J900.2
MUX_A: J901.1 U800.11(A)
MUX_B: J901.3 U800.10(B)
MUX_C: J901.5 U800.9(C)
RESET: J900.9
SCK: J900.13 U700.20(SCLK)
SCL: J900.17 R901.1
SDA: J900.19 R900.1
SDI: J901.12 U700.5(SDI)
SDO: J901.14 U700.7(SDO)
SIN1: R906.2
SIN1_flt: C900.1 J900.6 R906.1
SIN2: R908.2
SIN2_flt: C902.1 J900.10 R908.1
Tsense1: J800.5 U800.13(Y0)
Tsense2: J800.6 U800.14(Y1)
Tsense3: J800.7 U800.15(Y2)
Tsense4: J800.8 U800.12(Y3)
Tsense5: J800.9 U800.1(Y4)
Tsense6: J800.10 U800.5(Y5)
Tsense7: J800.11 U800.2(Y6)
Tsense8: J800.12 U800.4(Y7)
TsenseOut: R902.2 U800.3(COM)
V_supply: C600.1 C700.1 C702.1 U600.3(VIN) U700.16(VM) U700.21(VM)
V_track: C601.1 J800.3 J800.4 U600.4(VOUT)
VCC_3V3: C602.1 C701.1 C800.1 D900.1(K) R700.2 R701.1 R900.2 R901.2 R903.1 U600.1(ADJ/EN) U700.6(VDD) U800.16(VCC)
NetD700_1: D700.1(A) R700.1
NetD700_2: D700.2(K) R701.2 U700.12(~{FAULT})
NetD900_2: D900.2(A) D901.1(K) J900.14 R902.1

Not connected (* = marked no-connect by the designer): J900 3 5 7 11 15 16 18 20; J901 6 8 10 16 17 19

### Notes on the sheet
- 6. Power Supply for the Off-board Sensors
- 7. DC-Motor Driver for the Flap-Actuators
- Vsup: 4-40 V
  Iout: 50 mA
- 8. Sensor Signal Interface
- 9. LaunchPad Interface: MSP430F5529
- Vsup: 1.8-3.6 V
- (near J900) R903: optional
  will be populated if external supply is needed.
- Vsup: 2.5-5.5 V
  Isup: 40uA@5.5V
- (near C903) Optional filter circuit for analog signals.

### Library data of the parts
C600 C601 = CMP-0008021-2: CAP, CERM, 0.1 uF, 50 V, +/- 10%, X7R, AEC-Q200 Grade 1, 0805; Manufacturer: MuRata; TaMin_C: -55°C; Polarized: N; SizeAreaWB_mm2: 6.75; Value1: Unknown; U/M: EA; Value: 0.1uF; TaMax_C: 125°C; SizeZ_mm: 1.45; SizeX_mm: 2; SizeY_mm: 1.25; Cap_Case: 0805; Value2: 50V; SizeArea_mm2: 2.5; CompType: Capacitor; AEC Qualified: Y; Cap_F: 100nF; AEC Grade: 1; AEC Category: Q200
C602 C800 = CMP-0007106-4: as C302 on sheet HVA_HMI_p1
C700 C702 = CMP-0008380-2: as C107 on sheet HVA_HMI_p1
C701 = CMP-0076706-1: as C112 on sheet HVA_HMI_p1
C900-C903 = CMP-0007072-4: CAP, CERM, 220 pF, 20 V, +/- 5%, C0G/NP0, AEC-Q200 Grade 1, 0603; Manufacturer: TDK; TaMin_C: -55°C; Polarized: N; SizeAreaWB_mm2: 4.68; Value1: Unknown; U/M: EA; Value: 220pF; TaMax_C: 125°C; SizeZ_mm: 1; SizeX_mm: 1.6; SizeY_mm: 0.8; SizeArea_mm2: 1.28; AEC Qualified: Y; AEC Category: Q200
D700 = CMP-0002944-2: as D301 on sheet HVA_HMI_p1
D900 D901 = CMP-0029006-1: Diode, Ultrafast, 100 V, 0.25 A, SOD-323; Manufacturer: Nexperia; Io_A: 2.5dA; Green_Lifecycle: Not Set; SizeAreaWB_mm2: 8.695; Vr_V: 100V; Green_REACh: Incomplete; Value1: 0.25A; TJmax_C: 150°C; U/M: EA; Value: 100V; SizeZ_mm: 1; SizeX_mm: 2.7; SizeY_mm: 1.35; Vf_V: 1.4V; SizeArea_mm2: 3.645; AEC Category: Q101
J700 J800 = CMP-0055315-2: Header, 100mil, 6x2, SMT; Manufacturer: Molex; Green_Lifecycle: Active; Green_REACh: Passed
J900 J901 = CMP-0065001-1: Receptacle, 100mil, 10X2, Tin, TH; Manufacturer: FCI; CNHeader: False; Green_Lifecycle: Active; Green_REACh: Passed
R700 R906-R909 = CMP-0025946-3: as R301 on sheet HVA_HMI_p1
R701 = CMP-0025881-3: as R200 on sheet HVA_HMI_p1
R900 R901 = CMP-0025881-3: as R204 on sheet HVA_HMI_p1
R902 = CMP-0025700-4: RES, 100, 5%, 0.1 W, AEC-Q200 Grade 0, 0603; Manufacturer: Vishay-Dale; Power_W: 100mW; TempCo: 200 ppm/C; Value_Code: 100R; Value: 100; EIA_Code: E24; SizeX_mm: 1.6; SizeY_mm: 0.8; SizeZ_mm: 1; Value2: 0.1W; SizeArea_mm2: 1.28; AEC Qualified: Y; VDC_V: 75V; AEC Category: Q200; AEC Grade: 0
R903 = CMP-0020442-3: RES, 0, 5%, 0.125 W, AEC-Q200 Grade 0, 0805; Manufacturer: Vishay-Dale; Power_W: 125mW; TempCo: 200 ppm/C; Value_Code: 0000; Value: 0; EIA_Code: E24; SizeX_mm: 2; SizeY_mm: 1.25; SizeZ_mm: 1.45; Value2: 0.125W; SizeArea_mm2: 2.5; AEC Qualified: Y; VDC_V: 150V; AEC Category: Q200
U600 = CMP-0066933-1: 50-mA 40-V Voltage-Tracking LDO With 5-mV Tracking Tolerance, DBV0005A (SOT-23-5); Alternate Manufacturer: Texas Instruments; SizeAreaWB_mm2: 14.82; U/M: EA; SizeZ_mm: 1.45; SizeX_mm: 2.8; SizeY_mm: 2.9; SizeArea_mm2: 8.12; CompType: IC
U700 = CMP-0081858-1: Automotive Multi-Channel Half-Bridge Driver, PWP0024J (HTSSOP-24); Alternate Manufacturer: Texas Instruments; SizeAreaWB_mm2: 82.32; SizeZ_mm: 1.2; SizeX_mm: 6.4; SizeY_mm: 7.8; SizeArea_mm2: 49.92; CompType: IC; AEC Qualified: Y; AEC Category: Q200
U800 = CMP-0066256-1: Automotive Catalog 8-Channel Analog Multiplexer/Demultiplexer, PW0016A (TSSOP-16); Alternate Manufacturer: Texas Instruments; SizeAreaWB_mm2: 58.8; U/M: EA; SizeZ_mm: 1.2; SizeX_mm: 6.4; SizeY_mm: 5.0; SizeArea_mm2: 32.0; CompType: IC

## Sheet HVAC_HMI_EVM_Hardware.SchDoc
size 431 x 279 mm; Date: Not shown in title block; ApprovedBy: Not shown in title block; CheckedBy: Not shown in title block; Author: Not shown in title block; CompanyName: Not shown in title block; Engineer: Not shown in title block; Organization: Not shown in title block; Address1: Not shown in title block; Address2: Not shown in title block; Address3: Not shown in title block; Address4: Not shown in title block; DocumentNumber: 1; Revision: Use project parameter SCH_Rev; SheetNumber: 3; SheetTotal: 3; PageSetup: Record=PageOptions¦CenterHorizontal=True¦CenterVertical=True¦PrintScale=1.00¦XCorrection=1.00¦YCorrection=1.00¦PrintKind=0¦BorderSize=5000000¦LeftOffset=0¦BottomOffset=0¦Orientation=2¦PaperLength=1000¦PaperWidth=1000¦Scale=100¦PaperSource=15¦PrintQuality=600¦MediaType=1¦DitherType=10¦PaperKind=Letter¦PrintScaleMode=1
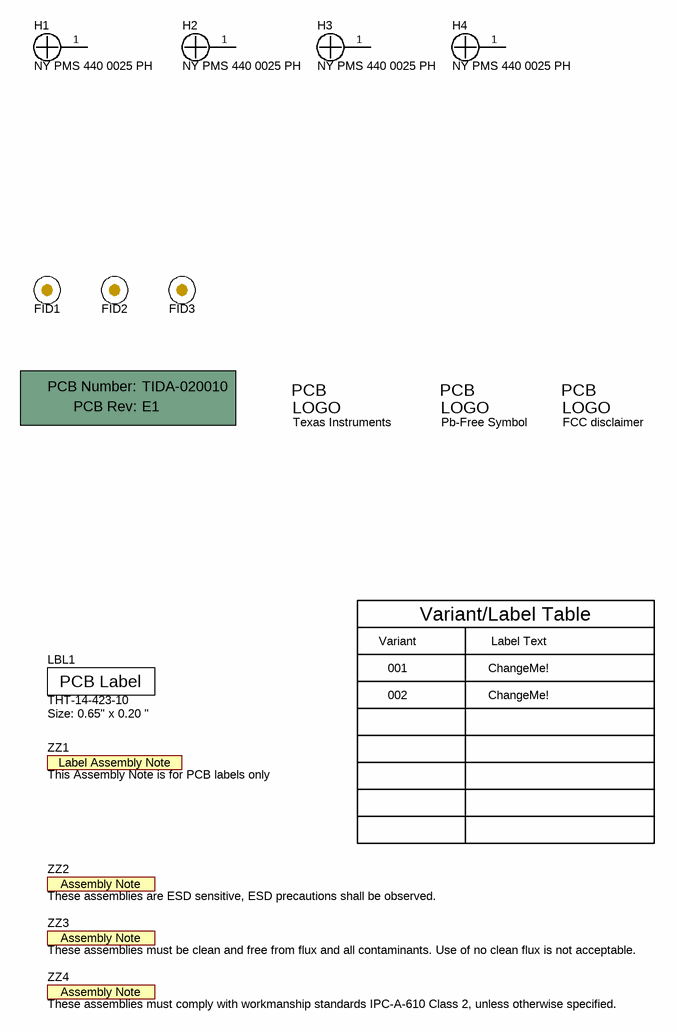
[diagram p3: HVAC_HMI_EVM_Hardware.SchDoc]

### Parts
!PCB  Printed Circuit Board  (value not drawn)  (mechanical)
FID1  Fiducial  [Fiducial10-20]  (value not drawn)
FID2  Fiducial  [Fiducial10-20]  (value not drawn)
FID3  Fiducial  [Fiducial10-20]  (value not drawn)
H1  NY PMS 440 0025 PH  [NY PMS 440 0025 PH]
H2  NY PMS 440 0025 PH  [NY PMS 440 0025 PH]
H3  NY PMS 440 0025 PH  [NY PMS 440 0025 PH]
H4  NY PMS 440 0025 PH  [NY PMS 440 0025 PH]
LBL1  THT-14-423-10  Note: Size: 0.65" x 0.20 "  [Label_650x200]
Logo1  Texas Instruments  [TI_Stacked_Overlay_Small]  (no BOM)
Logo2  Pb-Free Symbol  [Pb-Free_Overlay_Small]  (no BOM)
Logo3  FCC disclaimer  [FCC_disclaimer]  (no BOM)
ZZ1  This Assembly Note is for PCB labels only  [AssemblyNoteLabel]  (no BOM)
ZZ2  These assemblies are ESD sensitive, ESD precautions shall be observed.  [AssemblyNote]  (no BOM)
ZZ3  These assemblies must be clean and free from flux and all contaminants. Use of no clean flux is not acceptable.  [AssemblyNote]  (no BOM)
ZZ4  These assemblies must comply with workmanship standards IPC-A-610 Class 2, unless otherwise specified.  [AssemblyNote]  (no BOM)

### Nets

Not connected (* = marked no-connect by the designer): H1 1; H2 1; H3 1; H4 1

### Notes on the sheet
- Variant
- Variant/Label Table
- Label Text
- 001
- 002
- ChangeMe!

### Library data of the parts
!PCB = CMP-0003618-2: Manufacturer: Any; PartNumber: TIDA-020010
FID1-FID3 = CMP-0077181-1: Fiducial mark.  There is nothing to buy or mount.
H1-H4 = CMP-0003617-1: Machine Screw, Round, #4-40 x 1/4, Nylon, Philips panhead; Manufacturer: B&F Fastener Supply; CompType: Hardware
LBL1 = CMP-0003625-1: Thermal Transfer Printable Labels, 0.650" W x 0.200" H - 10,000 per roll; Manufacturer: Brady; CompType: Label
Logo1 = CMP-0074838-1: Texas Instrument Corporate Signature; SymbolCreator: a0412235; Lib Reference: TI_Logo; Library Reference: Logo
Logo2 = CMP-0074839-1: SymbolCreator: a0412235; Library Reference: Logo
Logo3 = CMP-0074847-1: FCC_disclaimer; Library Reference: Logo
ZZ1 = CMP-0003616-3
ZZ2 = CMP-0077236-1
ZZ3 = CMP-0077237-1
ZZ4 = CMP-0077238-1

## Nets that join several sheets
GND: HVA_HMI_p1 (42 pins), HVA_HMI_p2 (25 pins)
BLANK: HVA_HMI_p1 (U300.36), HVA_HMI_p2 (J901.11)
COS1: HVA_HMI_p1 (U502.2), HVA_HMI_p2 (R907.2)
COS2: HVA_HMI_p1 (U503.2), HVA_HMI_p2 (R909.2)
GCLK: HVA_HMI_p1 (U300.4 U300.5 U300.6), HVA_HMI_p2 (J901.4)
HS_DIAG: HVA_HMI_p1 (R201.2), HVA_HMI_p2 (J901.9)
HS_DIAG_STAT: HVA_HMI_p1 (R203.2), HVA_HMI_p2 (J901.15)
HS_IN: HVA_HMI_p1 (R200.2), HVA_HMI_p2 (J901.7)
LATCH: HVA_HMI_p1 (U300.3), HVA_HMI_p2 (J901.13)
SCK: HVA_HMI_p1 (U300.2), HVA_HMI_p2 (J900.13 U700.20)
SCL: HVA_HMI_p1 (U400.4), HVA_HMI_p2 (J900.17 R901.1)
SDA: HVA_HMI_p1 (U400.6), HVA_HMI_p2 (J900.19 R900.1)
SDI: HVA_HMI_p1 (U300.1), HVA_HMI_p2 (J901.12 U700.5)
SDO: HVA_HMI_p1 (U300.19), HVA_HMI_p2 (J901.14 U700.7)
SIN1: HVA_HMI_p1 (U500.2), HVA_HMI_p2 (R906.2)
SIN2: HVA_HMI_p1 (U501.2), HVA_HMI_p2 (R908.2)
V_supply: HVA_HMI_p1 (5 pins), HVA_HMI_p2 (6 pins)
VCC_3V3: HVA_HMI_p1 (44 pins), HVA_HMI_p2 (12 pins)

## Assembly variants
001: not fitted FID1 FID2 FID3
